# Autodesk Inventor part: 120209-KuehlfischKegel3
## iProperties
Created: 2012-02
Part Number: 120209-KuehlfischKegel3
Document SubType Name: Modeling
Designer: mp
Density: 1 g/cm^3
Author: mp
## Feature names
1. Umdrehung1 [Revolution]
2. Extrusion1
3. Wandstärke1
4. Rundung1 [Fillet]
5. Bohrung1 [Hole]
6. Spiegeln1 [Mirror]
7. Runde Anordnung1 [Circular Pattern]
